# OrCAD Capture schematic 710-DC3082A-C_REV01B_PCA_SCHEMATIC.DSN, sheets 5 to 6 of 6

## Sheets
5 PAGE2: size Custom; rev: V1.0; company: WITH DIGITAL POWER MANAGEMENT; note: POLYPHASE SINGLE OUTPUT DC/DC PSM
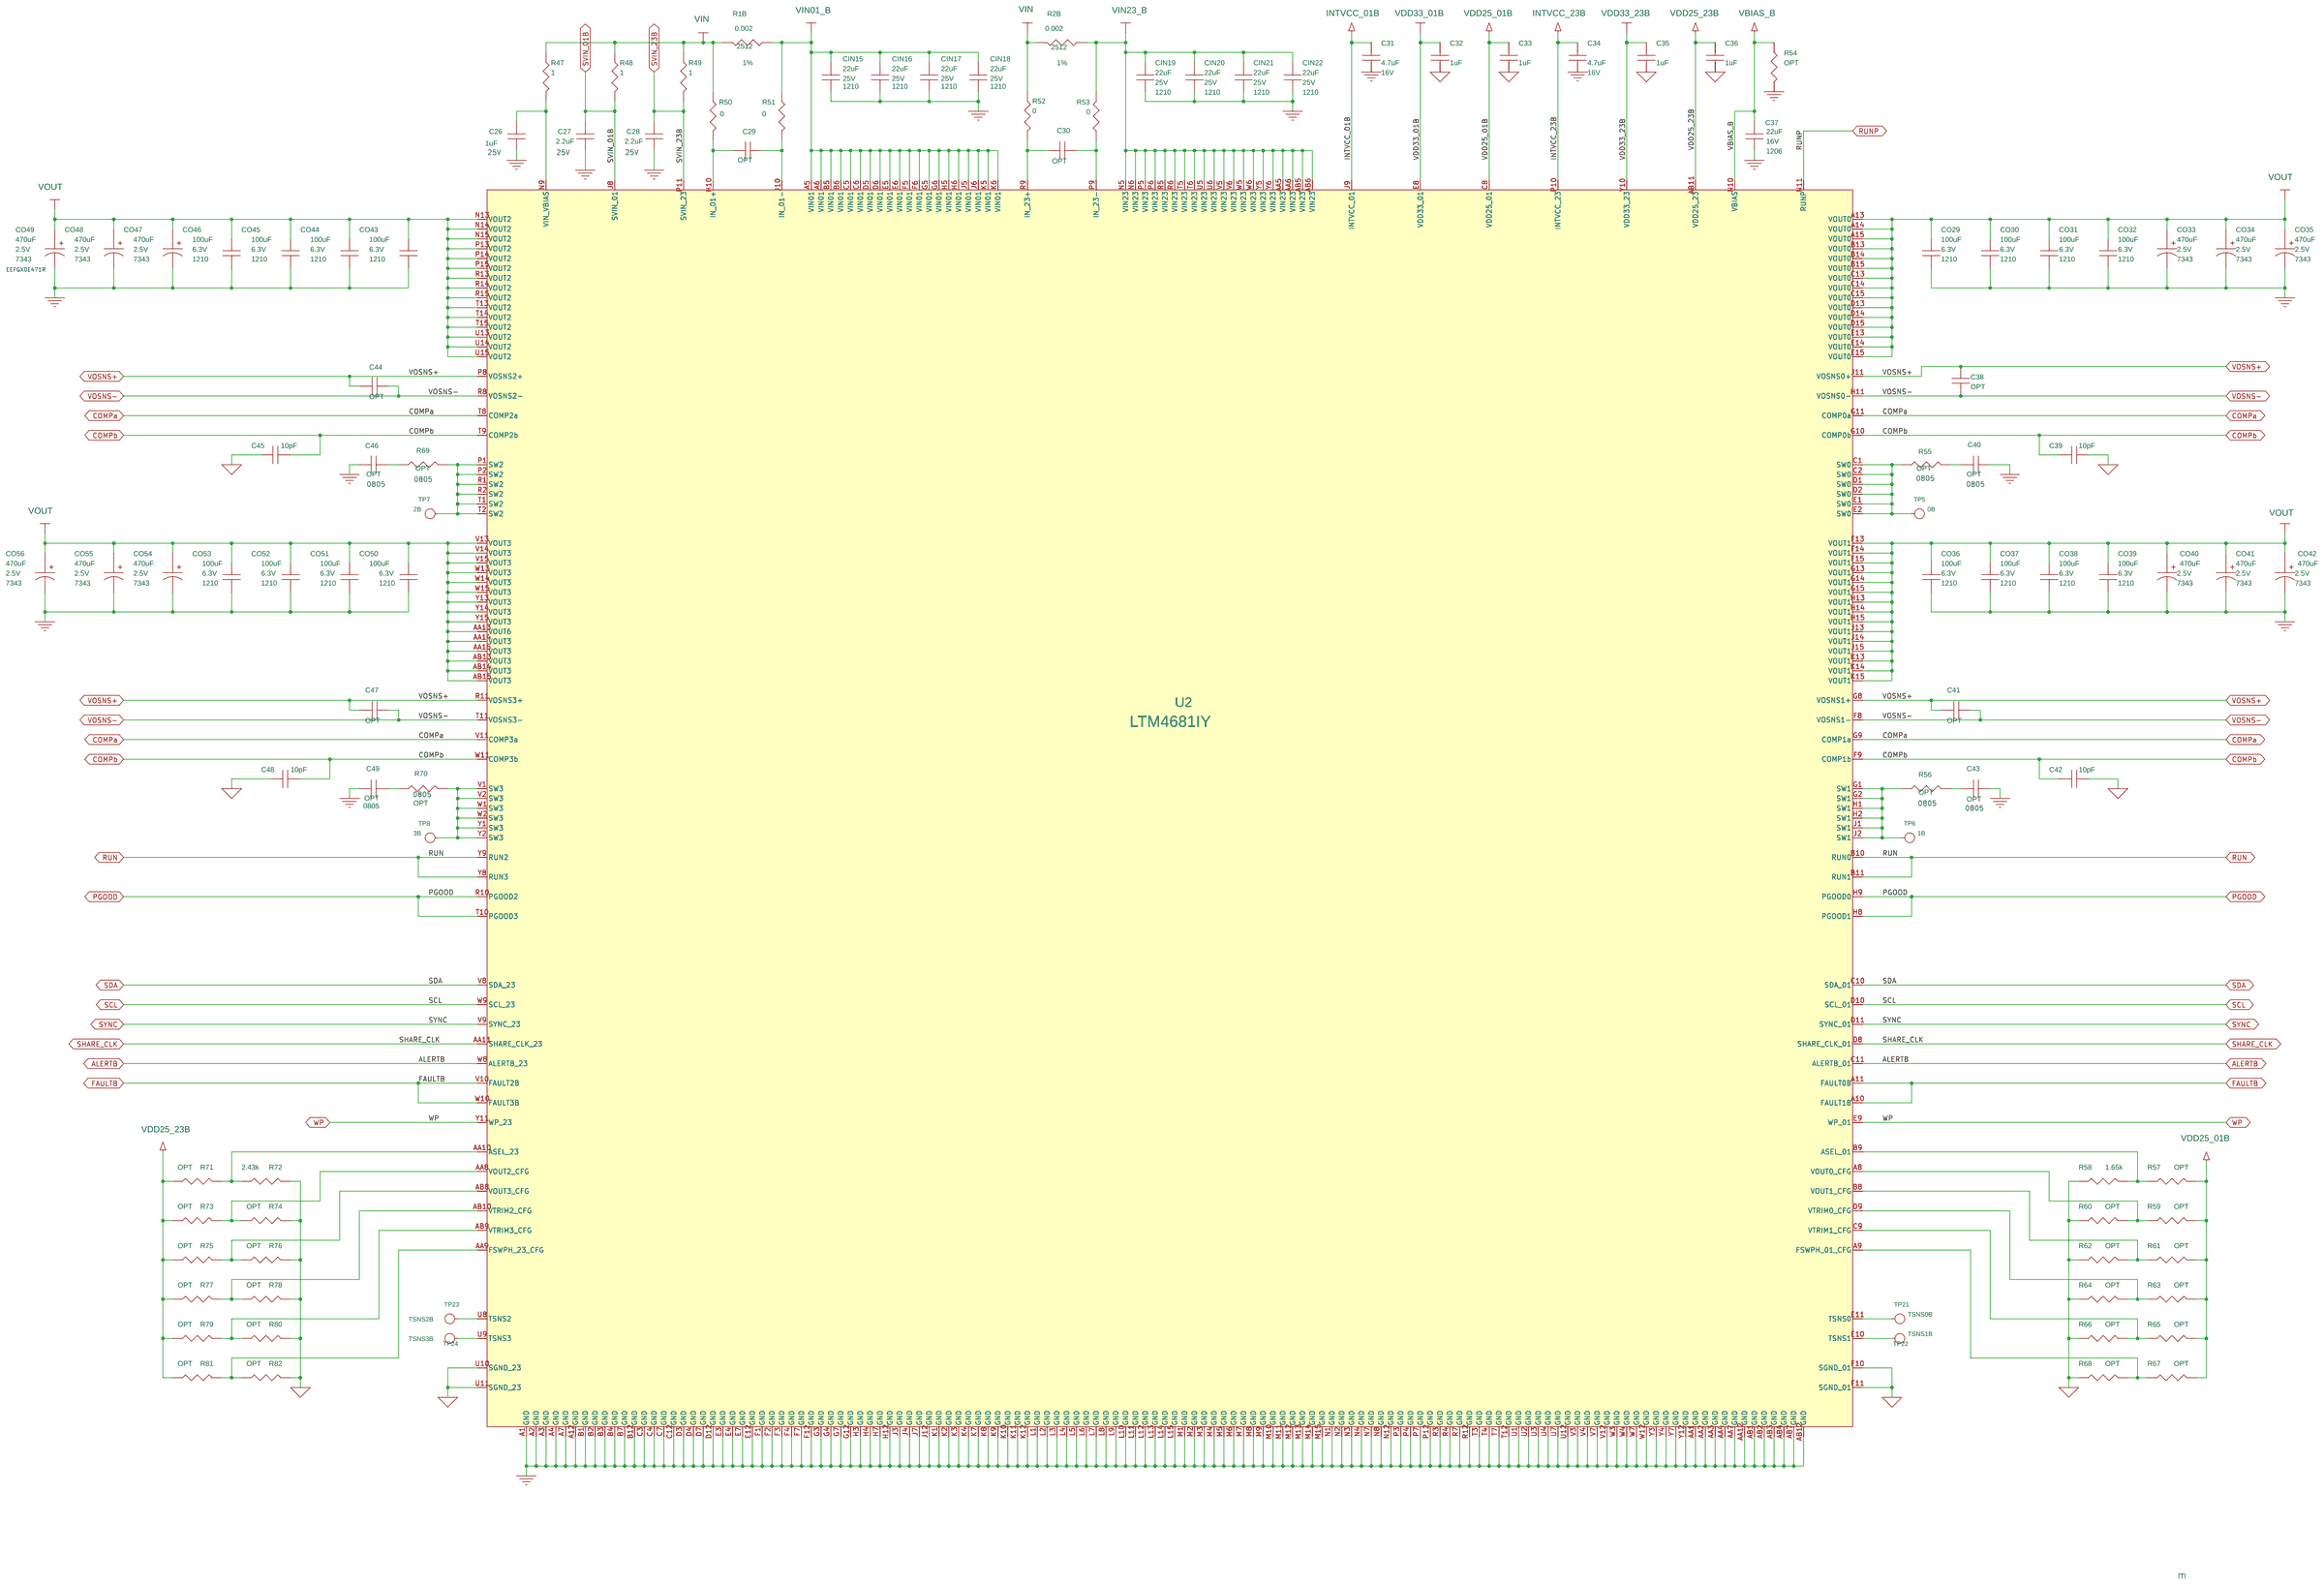
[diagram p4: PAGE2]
6 PAGE1: size Custom; rev: V1.0; company: WITH DIGITAL POWER MANAGEMENT; note: POLYPHASE SINGLE OUTPUT DC/DC PSM
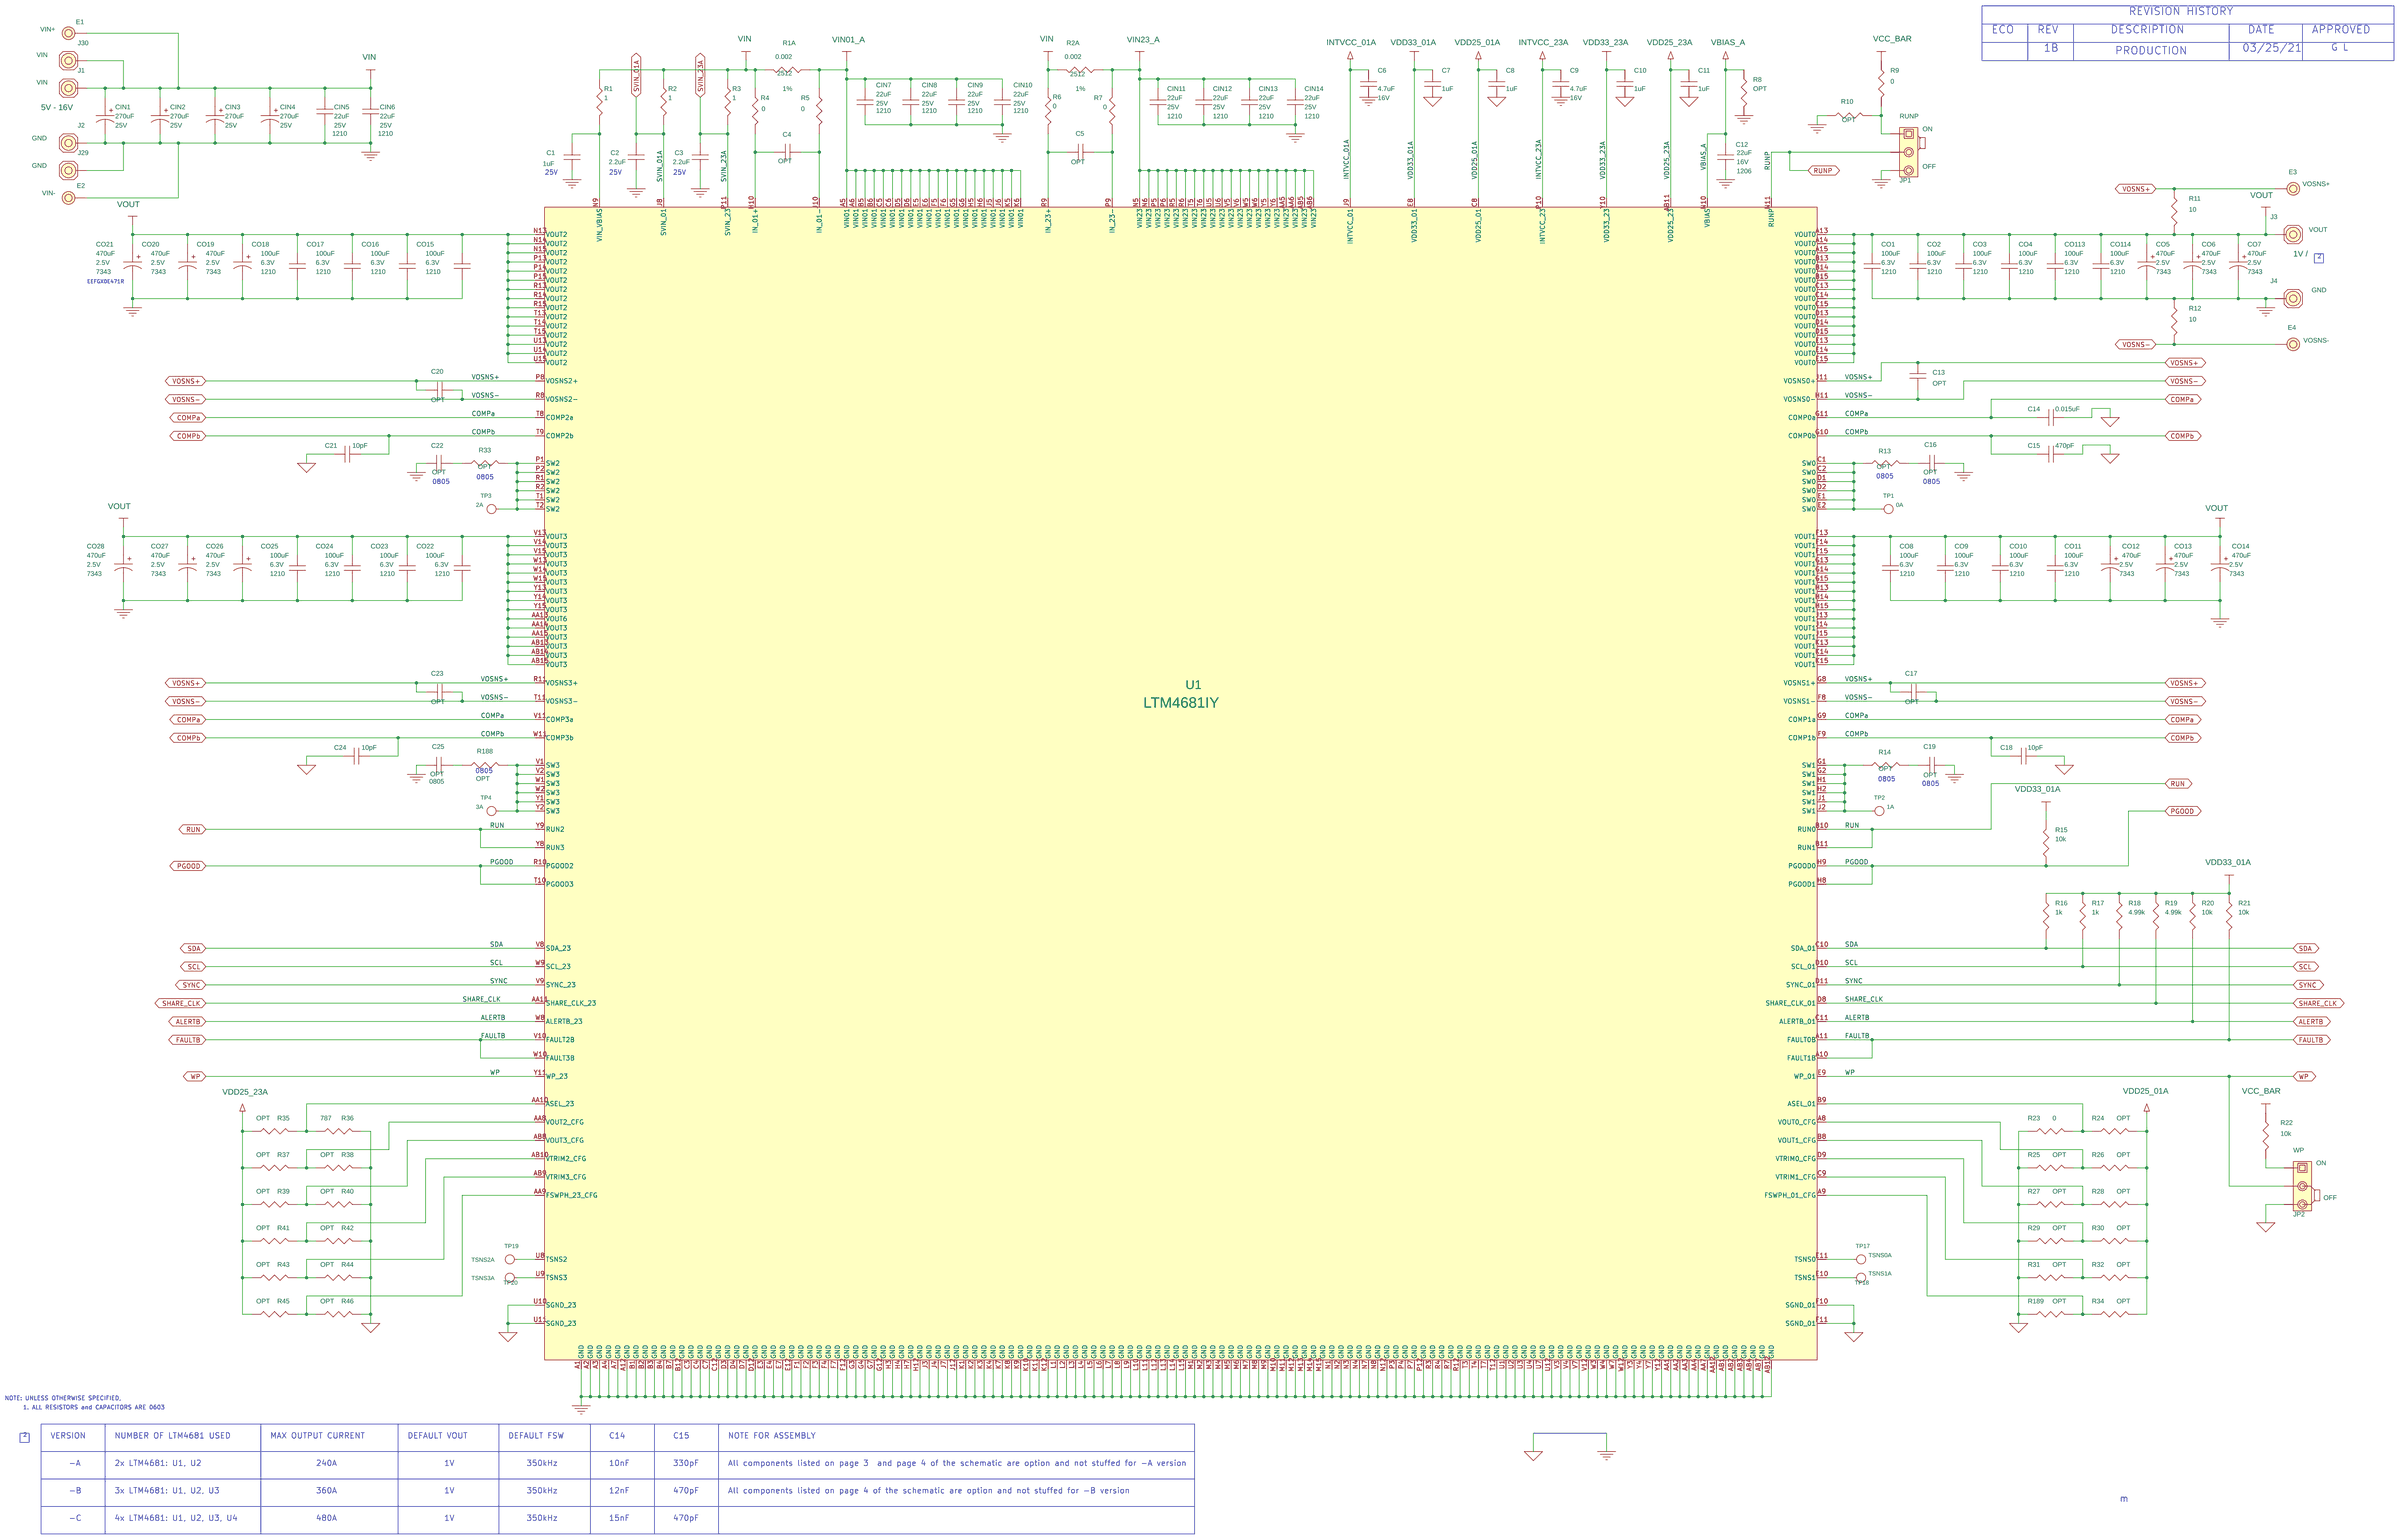
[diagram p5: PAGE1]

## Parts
sheet PAGE1
C1  1uF  [CC0603N]
C2  2.2uF  [CC0603N]
C3  2.2uF  [CC0603N]
C4  OPT  [CC0603N]
C5  OPT  [CC0603N]
C6  4.7uF  [CC0603N]
C7  1uF  [CC0603N]
C8  1uF  [CC0603N]
C9  4.7uF  [CC0603N]
C10  1uF  [CC0603N]
C11  1uF  [CC0603N]
C12  22uF  [CC1206N]
C13  OPT  [CC0603N]
C14  0.015uF  [CC0603N]
C15  470pF  [CC0603N]
C16  OPT  [CC0805N]
C17  OPT  [CC0603N]
C18  10pF  [CC0603N]
C19  OPT  [CC0805N]
C20  OPT  [CC0603N]
C21  10pF  [CC0603N]
C22  OPT  [CC0805N]
C23  OPT  [CC0603N]
C24  10pF  [CC0603N]
C25  OPT  [CC0805N]
CIN1  270uF  [PANASONIC_ZK_8X10.2]
CIN2  270uF  [PANASONIC_ZK_8X10.2]
CIN3  270uF  [PANASONIC_ZK_8X10.2]
CIN4  270uF  [PANASONIC_ZK_8X10.2]
CIN5  22uF  [CC1210N]
CIN6  22uF  [CC1210N]
CIN7  22uF  [CC1210N]
CIN8  22uF  [CC1210N]
CIN9  22uF  [CC1210N]
CIN10  22uF  [CC1210N]
CIN11  22uF  [CC1210N]
CIN12  22uF  [CC1210N]
CIN13  22uF  [CC1210N]
CIN14  22uF  [CC1210N]
CO1  100uF  [CC1210N]
CO2  100uF  [CC1210N]
CO3  100uF  [CC1210N]
CO4  100uF  [CC1210N]
CO5  470uF  [CAPMP7343N]
CO6  470uF  [CAPMP7343N]
CO7  470uF  [CAPMP7343N]
CO8  100uF  [CC1210N]
CO9  100uF  [CC1210N]
CO10  100uF  [CC1210N]
CO11  100uF  [CC1210N]
CO12  470uF  [CAPMP7343N]
CO13  470uF  [CAPMP7343N]
CO14  470uF  [CAPMP7343N]
CO15  100uF  [CC1210N]
CO16  100uF  [CC1210N]
CO17  100uF  [CC1210N]
CO18  100uF  [CC1210N]
CO19  470uF  [CAPMP7343N]
CO20  470uF  [CAPMP7343N]
CO21  470uF  [CAPMP7343N]
CO22  100uF  [CC1210N]
CO23  100uF  [CC1210N]
CO24  100uF  [CC1210N]
CO25  100uF  [CC1210N]
CO26  470uF  [CAPMP7343N]
CO27  470uF  [CAPMP7343N]
CO28  470uF  [CAPMP7343N]
CO113  100uF  [CC1210N]
CO114  100uF  [CC1210N]
E1  TEST POINT  [MILLMAX2501]
E2  TEST POINT  [MILLMAX2501]
E3  TEST POINT  [MILLMAX2501]
E4  TEST POINT  [MILLMAX2501]
J1  STUD,#10-32  [PENN-KFH-032]
J2  STUD,#10-32  [PENN-KFH-032]
J3  STUD,#10-32  [PENN-KFH-032]
J4  STUD,#10-32  [PENN-KFH-032]
J29  STUD,#10-32  [PENN-KFH-032]
J30  STUD,#10-32  [PENN-KFH-032]
JP1  HDR  [HD1X3-079]
JP2  HDR  [HD1X3-079]
R1  1  [CR0603N]
R1A  0.002  [CR2512N]
R2  1  [CR0603N]
R2A  0.002  [CR2512N]
R3  1  [CR0603N]
R4  0  [CR0603N]
R5  0  [CR0603N]
R6  0  [CR0603N]
R7  0  [CR0603N]
R8  OPT  [CR0603N]
R9  0  [CR0603N]
R10  OPT  [CR0603N]
R11  10  [CR0603N]
R12  10  [CR0603N]
R13  OPT  [CR0805N]
R14  OPT  [CR0805N]
R15  10k  [CR0603N]
R16  1k  [CR0603N]
R17  1k  [CR0603N]
R18  4.99k  [CR0603N]
R19  4.99k  [CR0603N]
R20  10k  [CR0603N]
R21  10k  [CR0603N]
R22  10k  [CR0603N]
R23  0  [CR0603N]
R24  OPT  [CR0603N]
R25  OPT  [CR0603N]
R26  OPT  [CR0603N]
R27  OPT  [CR0603N]
R28  OPT  [CR0603N]
R29  OPT  [CR0603N]
R30  OPT  [CR0603N]
R31  OPT  [CR0603N]
R32  OPT  [CR0603N]
R33  OPT  [CR0805N]
R34  OPT  [CR0603N]
R35  OPT  [CR0603N]
R36  787  [CR0603N]
R37  OPT  [CR0603N]
R38  OPT  [CR0603N]
R39  OPT  [CR0603N]
R40  OPT  [CR0603N]
R41  OPT  [CR0603N]
R42  OPT  [CR0603N]
R43  OPT  [CR0603N]
R44  OPT  [CR0603N]
R45  OPT  [CR0603N]
R46  OPT  [CR0603N]
R188  OPT  [CR0805N]
R189  OPT  [CR0603N]
TP1  0A  [TP-.762MM]
TP2  1A  [TP-.762MM]
TP3  2A  [TP-.762MM]
TP4  3A  [TP-.762MM]
TP17  TSNS0A  [TP-.762MM]
TP18  TSNS1A  [TP-.762MM]
TP19  TSNS2A  [TP-.762MM]
TP20  TSNS3A  [TP-.762MM]
U1  LTM4681IY  [LTC-BGA-330-4681Y]
XJP1  SHUNT
XJP4  SHUNT
sheet PAGE2
C26  1uF  [CC0603N]
C27  2.2uF  [CC0603N]
C28  2.2uF  [CC0603N]
C29  OPT  [CC0603N]
C30  OPT  [CC0603N]
C31  4.7uF  [CC0603N]
C32  1uF  [CC0603N]
C33  1uF  [CC0603N]
C34  4.7uF  [CC0603N]
C35  1uF  [CC0603N]
C36  1uF  [CC0603N]
C37  22uF  [CC1206N]
C38  OPT  [CC0603N]
C39  10pF  [CC0603N]
C40  OPT  [CC0805N]
C41  OPT  [CC0603N]
C42  10pF  [CC0603N]
C43  OPT  [CC0805N]
C44  OPT  [CC0603N]
C45  10pF  [CC0603N]
C46  OPT  [CC0805N]
C47  OPT  [CC0603N]
C48  10pF  [CC0603N]
C49  OPT  [CC0805N]
CIN15  22uF  [CC1210N]
CIN16  22uF  [CC1210N]
CIN17  22uF  [CC1210N]
CIN18  22uF  [CC1210N]
CIN19  22uF  [CC1210N]
CIN20  22uF  [CC1210N]
CIN21  22uF  [CC1210N]
CIN22  22uF  [CC1210N]
CO29  100uF  [CC1210N]
CO30  100uF  [CC1210N]
CO31  100uF  [CC1210N]
CO32  100uF  [CC1210N]
CO33  470uF  [CAPMP7343N]
CO34  470uF  [CAPMP7343N]
CO35  470uF  [CAPMP7343N]
CO36  100uF  [CC1210N]
CO37  100uF  [CC1210N]
CO38  100uF  [CC1210N]
CO39  100uF  [CC1210N]
CO40  470uF  [CAPMP7343N]
CO41  470uF  [CAPMP7343N]
CO42  470uF  [CAPMP7343N]
CO43  100uF  [CC1210N]
CO44  100uF  [CC1210N]
CO45  100uF  [CC1210N]
CO46  100uF  [CC1210N]
CO47  470uF  [CAPMP7343N]
CO48  470uF  [CAPMP7343N]
CO49  470uF  [CAPMP7343N]
CO50  100uF  [CC1210N]
CO51  100uF  [CC1210N]
CO52  100uF  [CC1210N]
CO53  100uF  [CC1210N]
CO54  470uF  [CAPMP7343N]
CO55  470uF  [CAPMP7343N]
CO56  470uF  [CAPMP7343N]
R1B  0.002  [CR2512N]
R2B  0.002  [CR2512N]
R47  1  [CR0603N]
R48  1  [CR0603N]
R49  1  [CR0603N]
R50  0  [CR0603N]
R51  0  [CR0603N]
R52  0  [CR0603N]
R53  0  [CR0603N]
R54  OPT  [CR0603N]
R55  OPT  [CR0805N]
R56  OPT  [CR0805N]
R57  OPT  [CR0603N]
R58  1.65k  [CR0603N]
R59  OPT  [CR0603N]
R60  OPT  [CR0603N]
R61  OPT  [CR0603N]
R62  OPT  [CR0603N]
R63  OPT  [CR0603N]
R64  OPT  [CR0603N]
R65  OPT  [CR0603N]
R66  OPT  [CR0603N]
R67  OPT  [CR0603N]
R68  OPT  [CR0603N]
R69  OPT  [CR0805N]
R70  OPT  [CR0805N]
R71  OPT  [CR0603N]
R72  2.43k  [CR0603N]
R73  OPT  [CR0603N]
R74  OPT  [CR0603N]
R75  OPT  [CR0603N]
R76  OPT  [CR0603N]
R77  OPT  [CR0603N]
R78  OPT  [CR0603N]
R79  OPT  [CR0603N]
R80  OPT  [CR0603N]
R81  OPT  [CR0603N]
R82  OPT  [CR0603N]
TP5  0B  [TP-.762MM]
TP6  1B  [TP-.762MM]
TP7  2B  [TP-.762MM]
TP8  3B  [TP-.762MM]
TP21  TSNS0B  [TP-.762MM]
TP22  TSNS1B  [TP-.762MM]
TP23  TSNS2B  [TP-.762MM]
TP24  TSNS3B  [TP-.762MM]
U2  LTM4681IY  [LTC-BGA-330-4681Y]

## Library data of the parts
C1 C7 C8 C10 C11 C26 C32 C33 C35 C36 = CAP: CAP.,1uF,X7R,25V,10%,0603,AEC-Q200; CLASS: DISCRETE; Dielectric Type: X7R; FPLIST: CC0603N,CC0603L,CC0603M; Inventory Qty: 53700; Manufacturer: MURATA; Manufacturer PN: GCM188R71E105KA64D; PART_NUMBER: 150-0291; Package Size: 0603; Rated Voltage: 25V; Tolerance: 10%
C2 C3 C27 C28 = CAP: CAP.,2.2uF,X5R,25V,10%,0603; CLASS: DISCRETE; Dielectric Type: X5R; FPLIST: CC0603N,CC0603L,CC0603M; Inventory Qty: 35022; Manufacturer: MURATA; Manufacturer PN: GRM188R61E225KA12D; PART_NUMBER: 150-3289; Package Size: 0603; Rated Voltage: 25V; Tolerance: 10%
C4 C5 C13 C17 C20 C23 C29 C30 C38 C41 C44 C47 = CAP: CAP., OPTION, 0603; CLASS: DISCRETE; FPLIST: CC0603N,CC0603L,CC0603M; PART_NUMBER: 150-3038; Package Size: 0603; Package Type: SMD
C6 C9 C31 C34 = CAP: CAP.,4.7uF,X5R,16V,10%,0603; CLASS: DISCRETE; Dielectric Type: X5R; FPLIST: CC0603N,CC0603L,CC0603M; Inventory Qty: 44050; Manufacturer: MURATA; Manufacturer PN: GRM188R61C475KAAJD; PART_NUMBER: 150-3182; Package Size: 0603; Rated Voltage: 16V; Tolerance: 10%
C12 C37 = CAP: CAP.,22uF,X5R,16V,10%,1206; CLASS: DISCRETE; Dielectric Type: X5R; FPLIST: CC1206N,CC1206L,CC1206M; Inventory Qty: 6429; Manufacturer: AVX; Manufacturer PN: 1206YD226KAT2A; PART_NUMBER: 150-3044; Package Size: 1206; Rated Voltage: 16V; Tolerance: 10%
C14 = CAP: CAP.,0.015uF,X7R,50V,5%,0603; CLASS: DISCRETE; Dielectric Type: X7R; FPLIST: CC0603N,CC0603L,CC0603M; Inventory Qty: 8000; Manufacturer: AVX; Manufacturer PN: 06035C153JAT2A; PART_NUMBER: 150-3084; Package Size: 0603; Package Type: SMD; Rated Voltage: 50V; Tolerance: 5%
C15 = CAP: CAP.,470pF,X7R,50V,10%,0603; CLASS: DISCRETE; Dielectric Type: X7R; FPLIST: CC0603N,CC0603L,CC0603M; Inventory Qty: 33012; Manufacturer: AVX; Manufacturer PN: 06035C471KAT2A; PART_NUMBER: 150-0125; Package Size: 0603; Rated Voltage: 50V; Tolerance: 10%
C16 C19 C22 C25 C40 C43 C46 C49 = CAP: CAP., OPTION, 0805; CLASS: DISCRETE; FPLIST: CC0805N,CC0805L,CC0805M; PART_NUMBER: 150-3036; Package Size: 0805; Package Type: SMD
C18 C21 C24 C39 C42 C45 C48 = CAP: CAP.,10pF,C0G,50V,5%,0603; CLASS: DISCRETE; Dielectric Type: C0G; FPLIST: CC0603N,CC0603L,CC0603M; Inventory Qty: 17004; Manufacturer: AVX; Manufacturer PN: 06035A100JAT2A; PART_NUMBER: 150-0280; Package Size: 0603; Rated Voltage: 50V; Tolerance: 5%
CIN1-CIN4 = CAP_P_ALT: CAP.,270uF,ALUM POLY HYB,25V,20%,8x10.2mm SMD,RADIAL,AEC-Q200,EEHZK; CLASS: DISCRETE; Dielectric Type: ALUM POLY HYB; Inventory Qty: 4798; Manufacturer: PANASONIC; Manufacturer PN: EEH-ZK1E271P; PART_NUMBER: 150-1740; Package Size: 8x10.2mm SMD,RADIAL; Rated Voltage: 25V; Tolerance: 20%
CIN5-CIN22 = CAP: CAP.,22uF,X5R,25V,10%,1210; CLASS: DISCRETE; Dielectric Type: X5R; FPLIST: CC1210N,CC1210L,CC1210M; Inventory Qty: 26336; Manufacturer: KEMET; Manufacturer PN: C1210C226K3PACTU; PART_NUMBER: 150-3033; Package Size: 1210; Package Type: SMD; Rated Voltage: 25V; Tolerance: 10%
CO1-CO4 CO8-CO11 CO15-CO18 CO22-CO25 CO29-CO32 CO36-CO39 CO43-CO46 CO50-CO53 CO113 CO114 = CAP: CAP.,100uF,X5R,6.3V,20%,1210; CLASS: DISCRETE; Dielectric Type: X5R; FPLIST: CC1210N,CC1210L,CC1210M; Inventory Qty: 50440; Manufacturer: AVX; Manufacturer PN: 12106D107MAT2A; PART_NUMBER: 150-3008; Package Size: 1210; Rated Voltage: 6.3V; Tolerance: 20%
CO5-CO7 CO12-CO14 CO19 CO20 CO26 CO27 CO33-CO35 CO40-CO42 CO47 CO48 CO54 CO55 = CAP_P_ALT: CAP.,470uF,TANT,POSCAP,2.5V,20%,7343,TPF Series; CLASS: DISCRETE; Dielectric Type: TANT,POSCAP; FPLIST: CAPMP7343N,CAPMP7343L,CAPMP7343M; Inventory Qty: 26416; Manufacturer: PANASONIC; Manufacturer PN: ETPF470M5H; PART_NUMBER: 150-2629; Package Size: 7343; Rated Voltage: 2.5V; Tolerance: 20%
CO21 CO49 = CAP_P_ALT: CAP.,470uF,TANT,POSCAP,2.5V,20%,7343,TPF Series; CLASS: DISCRETE; Dielectric Type: TANT,POSCAP; FPLIST: CAPMP7343N,CAPMP7343L,CAPMP7343M; Inventory Qty: 26416; Manufacturer: PANASONIC; Manufacturer PN: ETPF470M5H; PART_FIELD_01: 2.5V; PART_NUMBER: 150-2629; Package Size: 7343; Rated Voltage: 2.5V; Tolerance: 20%
CO28 CO56 = CAP_P_ALT: CAP.,470uF,TANT,POSCAP,2.5V,20%,7343,TPF Series; BOM Notes: COUT1,COUT6=6.3V; CLASS: DISCRETE; Dielectric Type: TANT,POSCAP; FPLIST: CAPMP7343N,CAPMP7343L,CAPMP7343M; Inventory Qty: 26416; Manufacturer: PANASONIC; Manufacturer PN: ETPF470M5H; PART_FIELD_01: 2.5V; PART_NUMBER: 150-2629; Package Size: 7343; Rated Voltage: 2.5V; Tolerance: 20%
E1 = TESTPOINT_1.219_MILL-MAX_2501: TEST POINT,TURRET,0.094" MTG. HOLE,PCB 0.062" THK; 9th Part Field: VIN+; CLASS: IO; Inventory Qty: 823526; Manufacturer: MILL-MAX; Manufacturer PN: 2501-2-00-80-00-00-07-0; PART_NUMBER: 260-0003
E2 = TESTPOINT_1.219_MILL-MAX_2501: TEST POINT,TURRET,0.094" MTG. HOLE,PCB 0.062" THK; 9th Part Field: VIN-; CLASS: IO; Inventory Qty: 823526; Manufacturer: MILL-MAX; Manufacturer PN: 2501-2-00-80-00-00-07-0; PART_NUMBER: 260-0003
E3 = TESTPOINT_1.219_MILL-MAX_2501: TEST POINT,TURRET,0.094" MTG. HOLE,PCB 0.062" THK; 5TH PART FIELD: VOSNS+; CLASS: IO; Inventory Qty: 823526; Manufacturer: MILL-MAX; Manufacturer PN: 2501-2-00-80-00-00-07-0; PART_NUMBER: 260-0003
E4 = TESTPOINT_1.219_MILL-MAX_2501: TEST POINT,TURRET,0.094" MTG. HOLE,PCB 0.062" THK; 5TH PART FIELD: VOSNS-; CLASS: IO; Inventory Qty: 823526; Manufacturer: MILL-MAX; Manufacturer PN: 2501-2-00-80-00-00-07-0; PART_NUMBER: 260-0003
J1 J30 = PEM-KFH: EVAL BOARD STUD HARDWARE SET, #10-32; 10th Part Field: 5V - 16V; 9th Part Field: VIN; CLASS: DISCRETE; Comments: CONSISTS OF QTY(1) STUD, 769-0012; QTY(1) RING LUG, 769-0013;QTY(2) HEX NUT,BRASS,761-0013; QTY(1) WASHER,#10 LOCK, 762-0021; Manufacturer: ANALOG DEVICES; Manufacturer PN: 720-0010; PART_NUMBER: 720-0010
J2 J4 J29 = PEM-KFH: EVAL BOARD STUD HARDWARE SET, #10-32; 9th Part Field: GND; CLASS: DISCRETE; Comments: CONSISTS OF QTY(1) STUD, 769-0012; QTY(1) RING LUG, 769-0013;QTY(2) HEX NUT,BRASS,761-0013; QTY(1) WASHER,#10 LOCK, 762-0021; Manufacturer: ANALOG DEVICES; Manufacturer PN: 720-0010; PART_NUMBER: 720-0010
J3 = PEM-KFH: EVAL BOARD STUD HARDWARE SET, #10-32; 10th Part Field: 1V /; 9th Part Field: VOUT; CLASS: DISCRETE; Comments: CONSISTS OF QTY(1) STUD, 769-0012; QTY(1) RING LUG, 769-0013;QTY(2) HEX NUT,BRASS,761-0013; QTY(1) WASHER,#10 LOCK, 762-0021; Manufacturer: ANALOG DEVICES; Manufacturer PN: 720-0010; PART_NUMBER: 720-0010
JP1 = 1X3_A: CONN.,HDR,MALE,1x3,2mm,VERT,ST,THT,NO SUBS. ALLOWED; 11th Part Field: OFF; 12th Part Field: RUNP; 9th Part Field: ON; CLASS: IO; Inventory Qty: 28997; Manufacturer: Wurth Elektronik; Manufacturer PN: 62000311121; PART_NUMBER: 250-0639
JP2 = 1X3_A: CONN.,HDR,MALE,1x3,2mm,VERT,ST,THT,NO SUBS. ALLOWED; 11th Part Field: OFF; 12th Part Field: WP; 9th Part Field: ON; CLASS: IO; Inventory Qty: 28997; Manufacturer: Wurth Elektronik; Manufacturer PN: 62000311121; PART_NUMBER: 250-0639
R1-R3 R47-R49 = RES: RES.,1 OHM,1%,1/10W,0603,AEC-Q200; CLASS: DISCRETE; FPLIST: CR0603N,CR0603L,CR0603M; Inventory Qty: 53360; Manufacturer: NIC; Manufacturer PN: NRC06F1R00TRF; PART_NUMBER: 100-0238; Package Size: 0603; Rated Power: 1/10W; Temperature Coefficient: 100ppm/C; Tolerance: 1%
R1A R1B R2A R2B = RES: RES.,0.002 OHM,1%,1W,2512,SENSE; CLASS: DISCRETE; FPLIST: CR2512N,CR2512L,CR2512M; Inventory Qty: 4998; Manufacturer: VISHAY; Manufacturer PN: WSL25122L000FEA; PART_NUMBER: 100-0062; Package Size: 2512; Rated Power: 1W; Temperature Coefficient: 275ppm/C; Tolerance: 1%
R4-R7 R9 R23 R50-R53 = RES: RES.,0 OHM,1/10W,0603,AEC-Q200; CLASS: DISCRETE; FPLIST: CR0603N,CR0603L,CR0603M; Inventory Qty: 700742; Manufacturer: VISHAY; Manufacturer PN: CRCW06030000Z0EA; PART_NUMBER: 100-0009; Package Size: 0603; Rated Power: 1/10W
R8 R10 R24-R32 R34 R35 R37-R46 R54 R57 R59-R68 R71 R73-R82 R189 = RES: RES., OPTION, 0603; CLASS: DISCRETE; FPLIST: CR0603N,CR0603L,CR0603M; PART_NUMBER: 100-2374; Package Size: 0603
R11 R12 = RES: RES.,10 OHMS,1%,1/10W,0603; CLASS: DISCRETE; FPLIST: CR0603N,CR0603L,CR0603M; Inventory Qty: 152750; Manufacturer: VISHAY; Manufacturer PN: CRCW060310R0FKEA; PART_NUMBER: 100-2306; Package Size: 0603; Rated Power: 1/10W; Temperature Coefficient: 100ppm/C; Tolerance: 1%
R13 R14 R33 R55 R56 R69 R70 R188 = RES: RES., OPTION, 0805; CLASS: DISCRETE; FPLIST: CR0805N,CR0805L,CR0805M; PART_NUMBER: 100-2558; Package Size: 0805
R15 R20-R22 = RES: RES.,10k OHMS,1%,1/10W,0603,AEC-Q200; CLASS: DISCRETE; FPLIST: CR0603N,CR0603L,CR0603M; Inventory Qty: 194448; Manufacturer: VISHAY; Manufacturer PN: CRCW060310K0FKEA; PART_NUMBER: 100-2012; Package Size: 0603; Rated Power: 1/10W; Temperature Coefficient: +/-100ppm/C; Tolerance: 1%
R16 R17 = RES: RES.,1k OHM,1%,1/10W,0603; CLASS: DISCRETE; FPLIST: CR0603N,CR0603L,CR0603M; Inventory Qty: 62420; Manufacturer: VISHAY; Manufacturer PN: CRCW06031K00FKEA; PART_NUMBER: 100-0136; Package Size: 0603; Rated Power: 1/10W; Temperature Coefficient: +/-100ppm; Tolerance: 1%
R18 R19 = RES: RES.,4.99k OHMS,1%,1/10W,0603,AEC-Q200; CLASS: DISCRETE; FPLIST: CR0603N,CR0603L,CR0603M; Inventory Qty: 89391; Manufacturer: PANASONIC; Manufacturer PN: ERJ3EKF4991V; PART_NUMBER: 100-2510; Package Size: 0603; Rated Power: 1/10W; Temperature Coefficient: 100ppm; Tolerance: 1%
R36 = RES: RES.,787 OHMS,1%,1/10W,0603; CLASS: DISCRETE; FPLIST: CR0603N,CR0603L,CR0603M; Inventory Qty: 19395; Manufacturer: NIC; Manufacturer PN: NRC06F7870TRF; PART_NUMBER: 100-2721; Package Size: 0603; Rated Power: 1/10W; Temperature Coefficient: 100ppm/C; Tolerance: 1%
TP1-TP8 TP17-TP24 = E-100SMT
U1 U2 = LTM4681-BGA_1: IC,QUAD OUTPUT uMODULE REG.,BGA; CLASS: IC; Inventory Qty: 0; Manufacturer: ANALOG DEVICES; Manufacturer PN: LTM4681EY#PBF; PART_NUMBER: LTM4681EY#PBF; Package Type: BGA
XJP1 XJP4 = SHUNT_2MM: CONN.,SHUNT,FEMALE,2 POS,2mm; CLASS: IO; Inventory Qty: 64675; Manufacturer: Wurth Elektronik; Manufacturer PN: 60800213421; PART_NUMBER: 250-0485
R58 = RES: RES.,1.65k OHMS,1%,1/10W,0603; CLASS: DISCRETE; FPLIST: CR0603N,CR0603L,CR0603M; Inventory Qty: 27055; Manufacturer: NIC; Manufacturer PN: NRC06F1651TRF; PART_NUMBER: 100-2723; Package Size: 0603; Rated Power: 1/10W; Temperature Coefficient: 100ppm/C; Tolerance: 1%
R72 = RES: RES.,2.43k OHMS,1%,1/10W,0603; CLASS: DISCRETE; FPLIST: CR0603N,CR0603L,CR0603M; Inventory Qty: 0; Manufacturer: YAGEO; Manufacturer PN: 9C06031A2431FKHFT; PART_NUMBER: 100-0087; Package Size: 0603; Rated Power: 1/10W; Tolerance: 1%

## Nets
GND: C1.1 C2.1 C3.1 C6.1 C9.1 C12.1 C16.1 C19.1 C22.1 C25.1 C26.1 C27.1 C28.1 C31.1 C34.1 C37.1 C40.1 C43.1 C46.1 C49.1 CIN1.2 CIN2.2 CIN3.2 CIN4.2 CIN5.1 CIN6.1 CIN7.1 CIN8.1 CIN9.1 CIN10.1 CIN11.1 CIN12.1 CIN13.1 CIN14.1 CIN15.1 CIN16.1 CIN17.1 CIN18.1 CIN19.1 CIN20.1 CIN21.1 CIN22.1 CO1.2 CO2.2 CO3.2 CO4.2 CO5.2 CO6.2 CO7.2 CO8.2 CO9.2 CO10.2 CO11.2 CO12.2 CO13.2 CO14.2 CO15.2 CO16.2 CO17.2 CO18.2 CO19.2 CO20.2 CO21.2 CO22.2 CO23.2 CO24.2 CO25.2 CO26.2 CO27.2 CO28.2 CO29.2 CO30.2 CO31.2 CO32.2 CO33.2 CO34.2 CO35.2 CO36.2 CO37.2 CO38.2 CO39.2 CO40.2 CO41.2 CO42.2 CO43.2 CO44.2 CO45.2 CO46.2 CO47.2 CO48.2 CO49.2 CO50.2 CO51.2 CO52.2 CO53.2 CO54.2 CO55.2 CO56.2 CO113.2 CO114.2 E2.1 J2.1 J4.1 J29.1 JP1.3 R8.2 R10.1 R12.1 R54.2 U1.A1(GND) U1.A2(GND) U1.A3(GND) U1.A4(GND) U1.A7(GND) U1.A12(GND) U1.AA1(GND) U1.AA2(GND) U1.AA3(GND) U1.AA4(GND) U1.AA7(GND) U1.AA12(GND) U1.AB1(GND) U1.AB2(GND) U1.AB3(GND) U1.AB4(GND) U1.AB7(GND) U1.AB12(GND) U1.B1(GND) U1.B2(GND) U1.B3(GND) U1.B4(GND) U1.B7(GND) U1.B12(GND) U1.C3(GND) U1.C4(GND) U1.C7(GND) U1.C12(GND) U1.D3(GND) U1.D4(GND) U1.D7(GND) U1.D12(GND) U1.E3(GND) U1.E4(GND) U1.E7(GND) U1.E12(GND) U1.F1(GND) U1.F2(GND) U1.F3(GND) U1.F4(GND) U1.F7(GND) U1.F12(GND) U1.G3(GND) U1.G4(GND) U1.G7(GND) U1.G12(GND) U1.H3(GND) U1.H4(GND) U1.H7(GND) U1.H12(GND) U1.J3(GND) U1.J4(GND) U1.J7(GND) U1.J12(GND) U1.K1(GND) U1.K2(GND) U1.K3(GND) U1.K4(GND) U1.K7(GND) U1.K8(GND) U1.K9(GND) U1.K10(GND) U1.K11(GND) U1.K12(GND) U1.L1(GND) U1.L2(GND) U1.L3(GND) U1.L4(GND) U1.L5(GND) U1.L6(GND) U1.L7(GND) U1.L8(GND) U1.L9(GND) U1.L10(GND) U1.L11(GND) U1.L12(GND) U1.L13(GND) U1.L14(GND) U1.L15(GND) U1.M1(GND) U1.M2(GND) U1.M3(GND) U1.M4(GND) U1.M5(GND) U1.M6(GND) U1.M7(GND) U1.M8(GND) U1.M9(GND) U1.M10(GND) U1.M11(GND) U1.M12(GND) U1.M13(GND) U1.M14(GND) U1.M15(GND) U1.N1(GND) U1.N2(GND) U1.N3(GND) U1.N4(GND) U1.N7(GND) U1.N8(GND) U1.N12(GND) U1.P3(GND) U1.P4(GND) U1.P7(GND) U1.P12(GND) U1.R3(GND) U1.R4(GND) U1.R7(GND) U1.R12(GND) U1.T3(GND) U1.T4(GND) U1.T7(GND) U1.T12(GND) U1.U1(GND) U1.U2(GND) U1.U3(GND) U1.U4(GND) U1.U7(GND) U1.U12(GND) U1.V3(GND) U1.V4(GND) U1.V7(GND) U1.V12(GND) U1.W3(GND) U1.W4(GND) U1.W7(GND) U1.W12(GND) U1.Y3(GND) U1.Y4(GND) U1.Y7(GND) U1.Y12(GND) U2.A1(GND) U2.A2(GND) U2.A3(GND) U2.A4(GND) U2.A7(GND) U2.A12(GND) U2.AA1(GND) U2.AA2(GND) U2.AA3(GND) U2.AA4(GND) U2.AA7(GND) U2.AA12(GND) U2.AB1(GND) U2.AB2(GND) U2.AB3(GND) U2.AB4(GND) U2.AB7(GND) U2.AB12(GND) U2.B1(GND) U2.B2(GND) U2.B3(GND) U2.B4(GND) U2.B7(GND) U2.B12(GND) U2.C3(GND) U2.C4(GND) U2.C7(GND) U2.C12(GND) U2.D3(GND) U2.D4(GND) U2.D7(GND) U2.D12(GND) U2.E3(GND) U2.E4(GND) U2.E7(GND) U2.E12(GND) U2.F1(GND) U2.F2(GND) U2.F3(GND) U2.F4(GND) U2.F7(GND) U2.F12(GND) U2.G3(GND) U2.G4(GND) U2.G7(GND) U2.G12(GND) U2.H3(GND) U2.H4(GND) U2.H7(GND) U2.H12(GND) U2.J3(GND) U2.J4(GND) U2.J7(GND) U2.J12(GND) U2.K1(GND) U2.K2(GND) U2.K3(GND) U2.K4(GND) U2.K7(GND) U2.K8(GND) U2.K9(GND) U2.K10(GND) U2.K11(GND) U2.K12(GND) U2.L1(GND) U2.L2(GND) U2.L3(GND) U2.L4(GND) U2.L5(GND) U2.L6(GND) U2.L7(GND) U2.L8(GND) U2.L9(GND) U2.L10(GND) U2.L11(GND) U2.L12(GND) U2.L13(GND) U2.L14(GND) U2.L15(GND) U2.M1(GND) U2.M2(GND) U2.M3(GND) U2.M4(GND) U2.M5(GND) U2.M6(GND) U2.M7(GND) U2.M8(GND) U2.M9(GND) U2.M10(GND) U2.M11(GND) U2.M12(GND) U2.M13(GND) U2.M14(GND) U2.M15(GND) U2.N1(GND) U2.N2(GND) U2.N3(GND) U2.N4(GND) U2.N7(GND) U2.N8(GND) U2.N12(GND) U2.P3(GND) U2.P4(GND) U2.P7(GND) U2.P12(GND) U2.R3(GND) U2.R4(GND) U2.R7(GND) U2.R12(GND) U2.T3(GND) U2.T4(GND) U2.T7(GND) U2.T12(GND) U2.U1(GND) U2.U2(GND) U2.U3(GND) U2.U4(GND) U2.U7(GND) U2.U12(GND) U2.V3(GND) U2.V4(GND) U2.V7(GND) U2.V12(GND) U2.W3(GND) U2.W4(GND) U2.W7(GND) U2.W12(GND) U2.Y3(GND) U2.Y4(GND) U2.Y7(GND) U2.Y12(GND) ; also on sheet 2 3 4
GND_SIGNAL: C7.1 C8.1 C10.1 C11.1 C14.1 C15.1 C18.1 C21.1 C24.1 C32.1 C33.1 C35.1 C36.1 C39.1 C42.1 C45.1 C48.1 JP2.3 R23.1 R25.1 R27.1 R29.1 R31.1 R36.1 R38.1 R40.1 R42.1 R44.1 R46.1 R58.1 R60.1 R62.1 R64.1 R66.1 R68.1 R72.1 R74.1 R76.1 R78.1 R80.1 R82.1 R189.1 U1.F10(SGND_01) U1.F11(SGND_01) U1.U10(SGND_23) U1.U11(SGND_23) U2.F10(SGND_01) U2.F11(SGND_01) U2.U10(SGND_23) U2.U11(SGND_23) ; also on sheet 2 3 4
SVIN_01A: C2.2 R2.2 U1.J8(SVIN_01) ; also on sheet 2
SVIN_01B: C27.2 R48.2 U2.J8(SVIN_01) ; also on sheet 2
SVIN_23A: C3.2 R3.2 U1.P11(SVIN_23) ; also on sheet 2
SVIN_23B: C28.2 R49.2 U2.P11(SVIN_23) ; also on sheet 2
VDD25_01A: C8.2 R24.2 R26.2 R28.2 R30.2 R32.2 R34.2 U1.C8(VDD25_01) ; also on sheet 2
VDD25_01B: C33.2 R57.2 R59.2 R61.2 R63.2 R65.2 R67.2 U2.C8(VDD25_01)
VDD25_23A: C11.2 R35.2 R37.2 R39.2 R41.2 R43.2 R45.2 U1.AB11(VDD25_23) ; also on sheet 2
VDD25_23B: C36.2 R71.2 R73.2 R75.2 R77.2 R79.2 R81.2 U2.AB11(VDD25_23)
VDD33_01A: C7.2 R15.2 R16.1 R17.1 R18.1 R19.1 R20.1 R21.1 R22.1 U1.E8(VDD33_01) ; also on sheet 2
VDD33_01B: C32.2 U2.E8(VDD33_01) ; also on sheet 2
VDD33_23A: C10.2 U1.Y10(VDD33_23) ; also on sheet 2
VDD33_23B: C35.2 U2.Y10(VDD33_23) ; also on sheet 2
VIN: CIN1.1 CIN2.1 CIN3.1 CIN4.1 CIN5.2 CIN6.2 E1.1 J1.1 J30.1 R1.1 R1A.1 R1B.1 R2.1 R2A.1 R2B.1 R3.1 R4.1 R6.1 R9.1 R47.1 R48.1 R49.1 R50.1 R52.1 ; also on sheet 2 3 4
VIN01_A: CIN7.2 CIN8.2 CIN9.2 CIN10.2 R1A.2 R5.1 U1.A5(VIN01) U1.A6(VIN01) U1.B5(VIN01) U1.B6(VIN01) U1.C5(VIN01) U1.C6(VIN01) U1.D5(VIN01) U1.D6(VIN01) U1.E5(VIN01) U1.E6(VIN01) U1.F5(VIN01) U1.F6(VIN01) U1.G5(VIN01) U1.G6(VIN01) U1.H5(VIN01) U1.H6(VIN01) U1.J5(VIN01) U1.J6(VIN01) U1.K5(VIN01) U1.K6(VIN01)
VIN01_B: CIN15.2 CIN16.2 CIN17.2 CIN18.2 R1B.2 R51.1 U2.A5(VIN01) U2.A6(VIN01) U2.B5(VIN01) U2.B6(VIN01) U2.C5(VIN01) U2.C6(VIN01) U2.D5(VIN01) U2.D6(VIN01) U2.E5(VIN01) U2.E6(VIN01) U2.F5(VIN01) U2.F6(VIN01) U2.G5(VIN01) U2.G6(VIN01) U2.H5(VIN01) U2.H6(VIN01) U2.J5(VIN01) U2.J6(VIN01) U2.K5(VIN01) U2.K6(VIN01)
VIN23_A: CIN11.2 CIN12.2 CIN13.2 CIN14.2 R2A.2 R7.1 U1.AA5(VIN23) U1.AA6(VIN23) U1.AB5(VIN23) U1.AB6(VIN23) U1.N5(VIN23) U1.N6(VIN23) U1.P5(VIN23) U1.P6(VIN23) U1.R5(VIN23) U1.R6(VIN23) U1.T5(VIN23) U1.T6(VIN23) U1.U5(VIN23) U1.U6(VIN23) U1.V5(VIN23) U1.V6(VIN23) U1.W5(VIN23) U1.W6(VIN23) U1.Y5(VIN23) U1.Y6(VIN23)
VIN23_B: CIN19.2 CIN20.2 CIN21.2 CIN22.2 R2B.2 R53.1 U2.AA5(VIN23) U2.AA6(VIN23) U2.AB5(VIN23) U2.AB6(VIN23) U2.N5(VIN23) U2.N6(VIN23) U2.P5(VIN23) U2.P6(VIN23) U2.R5(VIN23) U2.R6(VIN23) U2.T5(VIN23) U2.T6(VIN23) U2.U5(VIN23) U2.U6(VIN23) U2.V5(VIN23) U2.V6(VIN23) U2.W5(VIN23) U2.W6(VIN23) U2.Y5(VIN23) U2.Y6(VIN23)
ALERTB: R20.2 U1.C11(ALERTB_01) U1.W8(ALERTB_23) U2.C11(ALERTB_01) U2.W8(ALERTB_23) ; also on sheet 2 3 4
COMPa: C14.2 U1.G9(COMP1a) U1.G11(COMP0a) U1.T8(COMP2a) U1.V11(COMP3a) U2.G9(COMP1a) U2.G11(COMP0a) U2.T8(COMP2a) U2.V11(COMP3a) ; also on sheet 3 4
COMPb: C15.2 C18.2 C21.2 C24.2 C39.2 C42.2 C45.2 C48.2 U1.F9(COMP1b) U1.G10(COMP0b) U1.T9(COMP2b) U1.W11(COMP3b) U2.F9(COMP1b) U2.G10(COMP0b) U2.T9(COMP2b) U2.W11(COMP3b) ; also on sheet 3 4
FAULTB: R21.2 U1.A10(FAULT1B) U1.A11(FAULT0B) U1.V10(FAULT2B) U1.W10(FAULT3B) U2.A10(FAULT1B) U2.A11(FAULT0B) U2.V10(FAULT2B) U2.W10(FAULT3B) ; also on sheet 2 3 4
INTVCC_01A: C6.2 U1.J9(INTVCC_01) ; also on sheet 2
INTVCC_01B: C31.2 U2.J9(INTVCC_01) ; also on sheet 2
INTVCC_23A: C9.2 U1.P10(INTVCC_23) ; also on sheet 2
INTVCC_23B: C34.2 U2.P10(INTVCC_23) ; also on sheet 2
PGOOD: R15.1 U1.H8(PGOOD1) U1.H9(PGOOD0) U1.R10(PGOOD2) U1.T10(PGOOD3) U2.H8(PGOOD1) U2.H9(PGOOD0) U2.R10(PGOOD2) U2.T10(PGOOD3) ; also on sheet 2 3 4
RUN: U1.B10(RUN0) U1.B11(RUN1) U1.Y8(RUN3) U1.Y9(RUN2) U2.B10(RUN0) U2.B11(RUN1) U2.Y8(RUN3) U2.Y9(RUN2) ; also on sheet 2 3 4
RUNP: JP1.2 U1.N11(RUNP) U2.N11(RUNP) ; also on sheet 2 3 4
SCL: R17.2 U1.D10(SCL_01) U1.W9(SCL_23) U2.D10(SCL_01) U2.W9(SCL_23) ; also on sheet 2 3 4
SDA: R16.2 U1.C10(SDA_01) U1.V8(SDA_23) U2.C10(SDA_01) U2.V8(SDA_23) ; also on sheet 2 3 4
SHARE_CLK: R19.2 U1.AA11(SHARE_CLK_23) U1.D8(SHARE_CLK_01) U2.AA11(SHARE_CLK_23) U2.D8(SHARE_CLK_01) ; also on sheet 2 3 4
SYNC: R18.2 U1.D11(SYNC_01) U1.V9(SYNC_23) U2.D11(SYNC_01) U2.V9(SYNC_23) ; also on sheet 2 3 4
VBIAS_A: C12.2 R8.1 U1.N10(VBIAS)
VBIAS_B: C37.2 R54.1 U2.N10(VBIAS)
VOSNS+: C13.1 C17.2 C20.2 C23.2 C38.1 C41.2 C44.2 C47.2 E3.1 R11.1 U1.G8(VOSNS1+) U1.J11(VOSNS0+) U1.P8(VOSNS2+) U1.R11(VOSNS3+) U2.G8(VOSNS1+) U2.J11(VOSNS0+) U2.P8(VOSNS2+) U2.R11(VOSNS3+) ; also on sheet 3 4
VOSNS-: C13.2 C17.1 C20.1 C23.1 C38.2 C41.1 C44.1 C47.1 E4.1 R12.2 U1.F8(VOSNS1-) U1.H11(VOSNS0-) U1.R8(VOSNS2-) U1.T11(VOSNS3-) U2.F8(VOSNS1-) U2.H11(VOSNS0-) U2.R8(VOSNS2-) U2.T11(VOSNS3-) ; also on sheet 3 4
VOUT: CO1.1 CO2.1 CO3.1 CO4.1 CO5.1 CO6.1 CO7.1 CO8.1 CO9.1 CO10.1 CO11.1 CO12.1 CO13.1 CO14.1 CO15.1 CO16.1 CO17.1 CO18.1 CO19.1 CO20.1 CO21.1 CO22.1 CO23.1 CO24.1 CO25.1 CO26.1 CO27.1 CO28.1 CO29.1 CO30.1 CO31.1 CO32.1 CO33.1 CO34.1 CO35.1 CO36.1 CO37.1 CO38.1 CO39.1 CO40.1 CO41.1 CO42.1 CO43.1 CO44.1 CO45.1 CO46.1 CO47.1 CO48.1 CO49.1 CO50.1 CO51.1 CO52.1 CO53.1 CO54.1 CO55.1 CO56.1 CO113.1 CO114.1 J3.1 R11.2 U1.A13(VOUT0) U1.A14(VOUT0) U1.A15(VOUT0) U1.AA13(VOUT6) U1.AA14(VOUT3) U1.AA15(VOUT3) U1.AB13(VOUT3) U1.AB14(VOUT3) U1.AB15(VOUT3) U1.B13(VOUT0) U1.B14(VOUT0) U1.B15(VOUT0) U1.C13(VOUT0) U1.C14(VOUT0) U1.C15(VOUT0) U1.D13(VOUT0) U1.D14(VOUT0) U1.D15(VOUT0) U1.E13(VOUT0) U1.E14(VOUT0) U1.E15(VOUT0) U1.F13(VOUT1) U1.F14(VOUT1) U1.F15(VOUT1) U1.G13(VOUT1) U1.G14(VOUT1) U1.G15(VOUT1) U1.H13(VOUT1) U1.H14(VOUT1) U1.H15(VOUT1) U1.J13(VOUT1) U1.J14(VOUT1) U1.J15(VOUT1) U1.K13(VOUT1) U1.K14(VOUT1) U1.K15(VOUT1) U1.N13(VOUT2) U1.N14(VOUT2) U1.N15(VOUT2) U1.P13(VOUT2) U1.P14(VOUT2) U1.P15(VOUT2) U1.R13(VOUT2) U1.R14(VOUT2) U1.R15(VOUT2) U1.T13(VOUT2) U1.T14(VOUT2) U1.T15(VOUT2) U1.U13(VOUT2) U1.U14(VOUT2) U1.U15(VOUT2) U1.V13(VOUT3) U1.V14(VOUT3) U1.V15(VOUT3) U1.W13(VOUT3) U1.W14(VOUT3) U1.W15(VOUT3) U1.Y13(VOUT3) U1.Y14(VOUT3) U1.Y15(VOUT3) U2.A13(VOUT0) U2.A14(VOUT0) U2.A15(VOUT0) U2.AA13(VOUT6) U2.AA14(VOUT3) U2.AA15(VOUT3) U2.AB13(VOUT3) U2.AB14(VOUT3) U2.AB15(VOUT3) U2.B13(VOUT0) U2.B14(VOUT0) U2.B15(VOUT0) U2.C13(VOUT0) U2.C14(VOUT0) U2.C15(VOUT0) U2.D13(VOUT0) U2.D14(VOUT0) U2.D15(VOUT0) U2.E13(VOUT0) U2.E14(VOUT0) U2.E15(VOUT0) U2.F13(VOUT1) U2.F14(VOUT1) U2.F15(VOUT1) U2.G13(VOUT1) U2.G14(VOUT1) U2.G15(VOUT1) U2.H13(VOUT1) U2.H14(VOUT1) U2.H15(VOUT1) U2.J13(VOUT1) U2.J14(VOUT1) U2.J15(VOUT1) U2.K13(VOUT1) U2.K14(VOUT1) U2.K15(VOUT1) U2.N13(VOUT2) U2.N14(VOUT2) U2.N15(VOUT2) U2.P13(VOUT2) U2.P14(VOUT2) U2.P15(VOUT2) U2.R13(VOUT2) U2.R14(VOUT2) U2.R15(VOUT2) U2.T13(VOUT2) U2.T14(VOUT2) U2.T15(VOUT2) U2.U13(VOUT2) U2.U14(VOUT2) U2.U15(VOUT2) U2.V13(VOUT3) U2.V14(VOUT3) U2.V15(VOUT3) U2.W13(VOUT3) U2.W14(VOUT3) U2.W15(VOUT3) U2.Y13(VOUT3) U2.Y14(VOUT3) U2.Y15(VOUT3) ; also on sheet 2 3 4
WP: JP2.2 U1.E9(WP_01) U1.Y11(WP_23) U2.E9(WP_01) U2.Y11(WP_23) ; also on sheet 3 4
N21382349: C1.2 R1.2 U1.N9(VIN_VBIAS)
N21389813: C4.2 R4.2 U1.H10(IN_01+)
N21389816: C4.1 R5.2 U1.J10(IN_01-)
N21395887: C5.2 R6.2 U1.R9(IN_23+)
N21408483: C5.1 R7.2 U1.P9(IN_23-)
N21431561: JP1.1 R9.2 R10.2
N21472624: R13.1 TP1.1(A) U1.C1(SW0) U1.C2(SW0) U1.D1(SW0) U1.D2(SW0) U1.E1(SW0) U1.E2(SW0)
N21487261: R14.1 TP2.1(A) U1.G1(SW1) U1.G2(SW1) U1.H1(SW1) U1.H2(SW1) U1.J1(SW1) U1.J2(SW1)
N21487379: C19.2 R14.2
N21515478: R25.2 R26.1 U1.A8(VOUT0_CFG)
N21517814: R27.2 R28.1 U1.B8(VOUT1_CFG)
N21517925: R29.2 R30.1 U1.D9(VTRIM0_CFG)
N21518062: R31.2 R32.1 U1.C9(VTRIM1_CFG)
N21518084: R34.1 R189.2 U1.A9(FSWPH_01_CFG)
N21518290: R23.2 R24.1 U1.B9(ASEL_01)
N21537986: TP18.1(A) U1.E10(TSNS1)
N21554155: R33.1 TP3.1(A) U1.P1(SW2) U1.P2(SW2) U1.R1(SW2) U1.R2(SW2) U1.T1(SW2) U1.T2(SW2)
N21563513: R188.1 TP4.1(A) U1.V1(SW3) U1.V2(SW3) U1.W1(SW3) U1.W2(SW3) U1.Y1(SW3) U1.Y2(SW3)
N21563751: C25.2 R188.2
N21569954: R35.1 R36.2 U1.AA10(ASEL_23)
N21569988: R39.1 R40.2 U1.AB8(VOUT3_CFG)
N21570008: R41.1 R42.2 U1.AB10(VTRIM2_CFG)
N21570032: R37.1 R38.2 U1.AA8(VOUT2_CFG)
N21570040: R43.1 R44.2 U1.AB9(VTRIM3_CFG)
N21570064: R45.1 R46.2 U1.AA9(FSWPH_23_CFG)
N21570170: TP19.1(A) U1.U8(TSNS2)
N21570190: TP20.1(A) U1.U9(TSNS3)
N21838591: C16.2 R13.2
N22173279: C22.2 R33.2
N22451849: TP17.1(A) U1.E11(TSNS0)
N22478456: JP2.1 R22.2
N22513475: C26.2 R47.2 U2.N9(VIN_VBIAS)
N22513486: C29.2 R50.2 U2.H10(IN_01+)
N22513487: C29.1 R51.2 U2.J10(IN_01-)
N22513500: C30.2 R52.2 U2.R9(IN_23+)
N22513501: C30.1 R53.2 U2.P9(IN_23-)
N22513685: R55.1 TP5.1(A) U2.C1(SW0) U2.C2(SW0) U2.D1(SW0) U2.D2(SW0) U2.E1(SW0) U2.E2(SW0)
N22513749: R56.1 TP6.1(A) U2.G1(SW1) U2.G2(SW1) U2.H1(SW1) U2.H2(SW1) U2.J1(SW1) U2.J2(SW1)
N22513756: C43.2 R56.2
N22513784: R59.1 R60.2 U2.A8(VOUT0_CFG)
N22513787: R61.1 R62.2 U2.B8(VOUT1_CFG)
N22513790: R63.1 R64.2 U2.D9(VTRIM0_CFG)
N22513793: R65.1 R66.2 U2.C9(VTRIM1_CFG)
N22513796: R67.1 R68.2 U2.A9(FSWPH_01_CFG)
N22513798: R57.1 R58.2 U2.B9(ASEL_01)
N22513859: TP22.1(A) U2.E10(TSNS1)
N22513905: R69.1 TP7.1(A) U2.P1(SW2) U2.P2(SW2) U2.R1(SW2) U2.R2(SW2) U2.T1(SW2) U2.T2(SW2)
N22513961: R70.1 TP8.1(A) U2.V1(SW3) U2.V2(SW3) U2.W1(SW3) U2.W2(SW3) U2.Y1(SW3) U2.Y2(SW3)
N22513972: C49.2 R70.2
N22513981: R71.1 R72.2 U2.AA10(ASEL_23)
N22513984: R75.1 R76.2 U2.AB8(VOUT3_CFG)
N22513992: R77.1 R78.2 U2.AB10(VTRIM2_CFG)
N22513996: R73.1 R74.2 U2.AA8(VOUT2_CFG)
N22513999: R79.1 R80.2 U2.AB9(VTRIM3_CFG)
N22514003: R81.1 R82.2 U2.AA9(FSWPH_23_CFG)
N22514029: TP23.1(A) U2.U8(TSNS2)
N22514035: TP24.1(A) U2.U9(TSNS3)
N22514362: C40.2 R55.2
N22514417: C46.2 R69.2
N22514477: TP21.1(A) U2.E11(TSNS0)

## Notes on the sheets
sheet 5
- 25V
- 25V
- 25V
- EEFGX0E471R
- 0805
- 0805
- 0805
- 0805
- 0805
- 0805
- 0805
- m
sheet 6
- REVISION HISTORY
- ECO
- REV
- DESCRIPTION
- DATE
- APPROVED
- 1B
- PRODUCTION
- 03/25/21
- G L
- 25V
- 25V
- 25V
- 2
- EEFGX0E471R
- 0805
- 0805
- 0805
- 0805
- 0805
- 0805
- 0805
- NOTE: UNLESS OTHERWISE SPECIFIED,
- 1. ALL RESISTORS and CAPACITORS ARE 0603
- 2
- VERSION
- NUMBER OF LTM4681 USED
- MAX OUTPUT CURRENT
- DEFAULT VOUT
- DEFAULT FSW
- C14
- C15
- NOTE FOR ASSEMBLY
- -A
- 2x LTM4681: U1, U2
- 240A
- 1V
- 350kHz
- 10nF
- 330pF
- All components listed on page 3  and page 4 of the schematic are option and not stuffed for -A version
- -B
- 3x LTM4681: U1, U2, U3
- 360A
- 1V
- 350kHz
- 12nF
- 470pF
- All components listed on page 4 of the schematic are option and not stuffed for -B version
- m
- -C
- 4x LTM4681: U1, U2, U3, U4
- 480A
- 1V
- 350kHz
- 15nF
- 470pF
